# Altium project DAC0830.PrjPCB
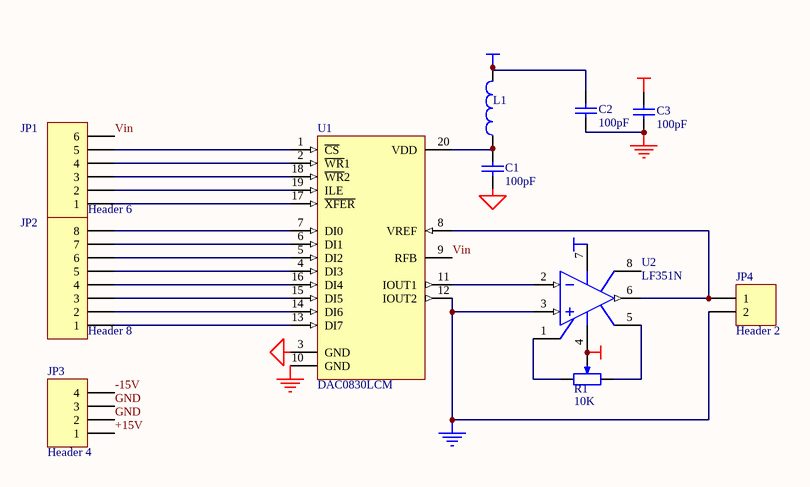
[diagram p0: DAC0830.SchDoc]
1 sheet, 11 parts. Net scope: global (net labels, ports and power ports of the same name join across sheets).
Board file: DAC0830.PcbDoc

## Sheet DAC0830.SchDoc
size A4

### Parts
C1  100pF  [CC2012-0805]
C2  100pF  [CC2012-0805]
C3  100pF  [CC2012-0805]
JP1  Header 6  [HDR1X6]
JP2  Header 8  [HDR1X8]
JP3  Header 4  [HDR1X4]
JP4  Header 2  [HDR1X2]
L1  Inductor  [C1005-0402]  (value not drawn)
R1  10K  [VR5]
U1  DAC0830LCM  [SO-G20]
U2  LF351N  [DIP-8]

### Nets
+15V: C2.2 JP3.1 L1.2 U2.7(V+)
-15V: C3.2 JP3.4 R1.3(TAP) U2.4(V-)
DGND: C1.1 U1.3(GND)
GND: C2.1 C3.1 JP3.2 JP3.3 JP4.2 U1.10(GND) U1.12(IOUT2) U2.3(IN+)
Vin: JP1.6 U1.9(RFB)
NetC1_2: C1.2 L1.1 U1.20(VDD)
NetJP1_1: JP1.1 U1.17(~{XFER})
NetJP1_2: JP1.2 U1.19(ILE)
NetJP1_3: JP1.3 U1.18(~{WR}2)
NetJP1_4: JP1.4 U1.2(~{WR}1)
NetJP1_5: JP1.5 U1.1(~{CS})
NetJP2_1: JP2.1 U1.13(DI7)
NetJP2_2: JP2.2 U1.14(DI6)
NetJP2_3: JP2.3 U1.15(DI5)
NetJP2_4: JP2.4 U1.16(DI4)
NetJP2_5: JP2.5 U1.4(DI3)
NetJP2_6: JP2.6 U1.5(DI2)
NetJP2_7: JP2.7 U1.6(DI1)
NetJP2_8: JP2.8 U1.7(DI0)
NetJP4_1: JP4.1 U1.8(VREF) U2.6(OUT)
NetR1_1: R1.1(TOP) U2.5(BAL)
NetR1_2: R1.2(BOT) U2.1(BAL)
NetU1_11: U1.11(IOUT1) U2.2(IN-)

Not connected (* = marked no-connect by the designer): U2 8(NC)

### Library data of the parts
C1-C3 = Cap: Capacitor; Manufacturer: Generic Components; Class I: Passive
JP1 = Header 6: Header, 6-Pin; Manufacturer: Generic Components; Class I: Connector
JP2 = Header 8: Header, 8-Pin; Manufacturer: Generic Components; Class I: Connector
JP3 = Header 4: Header, 4-Pin; Manufacturer: Generic Components; Class I: Connector
JP4 = Header 2: Header, 2-Pin; Manufacturer: Generic Components; Class I: Connector
L1 = Inductor: Manufacturer: Generic Components; Class I: Passive
R1 = RPot2: Potentiometer; Manufacturer: Generic Components; Class I: Passive; Set Position: 0.5
U1 = DAC0830LCM: 8-Bit µP-Compatible, Double-Buffered Digital-to-Analog Converter; Manufacturer: National Semiconductor; Package Information: Latest Revision: 2000; Class II: Digital to Analog
U2 = LF351N: Wide-Bandwidth JFET Input Operational Amplifier; Manufacturer: National Semiconductor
